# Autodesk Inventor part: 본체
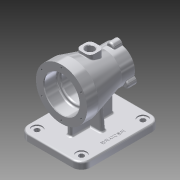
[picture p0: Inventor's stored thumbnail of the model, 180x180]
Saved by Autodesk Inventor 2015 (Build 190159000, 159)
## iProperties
Created: 2021-10
Part Number: 본체
Material: 알루미늄 6061
Document SubType Name: Modeling
Designer: 10259o
Density: 2.7 g/cm^3
Appearance: 알루미늄 - 평지
Mass: 1228.33 g
Surface Area: 906.538 cm^2
Volume: 454.938 cm^3
Author: 10259o
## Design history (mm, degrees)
sketch "스케치1"
  geometry: L1 (0, -100)-(0, 0); L2 (31, 0)-(31, -23); L3 (31, -23)-(25, -23); L4 (25, -23)-(25, -70); L5 (25, -70)-(19, -70); L6 (19, -70)-(19, -100); L7 (19, -100)-(29, -100); L8 (29, -100)-(29, -77); L9 (29, -77)-(45, -20); L10 (45, -20)-(45, 0); L11 (45, 0)-(31, 0); 2 further points
  constraints: 22 end point, 5 perpendicular, 2 horizontal alignment, 2 midpoint, 1 horizontal, 1 parallel, 1 vertical
  dimensions: "d0" = 100 distance between parallel lines of L7 L11; "d2" = 38 diameter of L6 L1; "d3" = 30 distance between parallel lines of L5 L7; "d4" = 47 distance between parallel lines of L3 L5; "d5" = 50 diameter of L4 L1; "d6" = 62 diameter of L2 L1; "d7" = 90 diameter of L10 L1; "d8" = 23 distance from line of L8.end L7; "d9" = 20 distance of L9.end L10.end; "d10" = 58 diameter of L8 L1
revolve "회전1" sketch "스케치1" stored, may be unused: angle "d11" = 90 deg
node "작업 평면1"
sketch "스케치2"
  geometry: L1 (55, -120)-(-55, -120); L2 (-55, -120)-(-55, 20); L3 (-55, 20)-(55, 20); L4 (55, 20)-(55, -120); L5 (55, -50)-(-55, -50); L6 (0, 0)-(0, -99.524); 1 further point
  constraints: 12 end point, 3 midpoint, 2 parallel, 1 horizontal, 1 perpendicular, 1 vertical, 1 vertical alignment
  dimensions: "d13" = 140 distance between parallel lines of L1 L3; "d14" = 110 distance of L2.end L3.end; "d15" = 50 distance from line of L5 L6.start
extrude "돌출1" join sketch "스케치2" distance "d16" = 12; taper "d17" = 0 deg
sketch "스케치3"
  geometry: L1 (-4, 13)-(4, 13); L2 (4, 13)-(4, 87); L3 (4, 87)-(-4, 87); L4 (-4, 87)-(-4, 13); L5 (-55, -20)-(-55, 120) reference; L6 (-55, 50)-(55, 50); L7 (55, 120)-(55, -20) reference; 2 further points
  constraints: 10 end point, 3 midpoint, 2 parallel, 1 horizontal, 1 perpendicular, 1 vertical alignment
  dimensions: "d18" = 8 distance of L2.end L3.end; "d19" = 74 distance between parallel lines of L1 L3; "d20" = 37 distance between parallel lines of L3 L6
extrude "돌출2" join sketch "스케치3" stored distance "d21" = 0; taper "d22" = 0 deg
node "작업 평면2"
sketch "스케치4"
  geometry: L1 (0, 12)-(110, 12) reference; L2 (79, 12)-(75.149, 56.019); L3 (75.149, 56.019)-(59, 56.019); L4 (59, 12)-(59, 53.277) reference; L5 (59, 56.019)-(59, 12); 1 further point
  constraints: 6 end point, 2 point on line, 1 collinear, 1 horizontal
  dimensions: "d24" = 95 deg angle of L1 L2; "d91" = 24 horizontal distance of point (55, 82) L2.start
extrude "돌출3" join sketch "스케치4" stored distance "d26" = 8; taper "d27" = 0 deg
node "작업 평면3"
sketch "스케치5"
  geometry: L1 (12.5, -62.5)-(-12.5, -62.5); L2 (-12.5, -62.5)-(-12.5, -37.5); L3 (-12.5, -37.5)-(12.5, -37.5); L4 (12.5, -37.5)-(12.5, -62.5); L5 (-55, -120)-(-55, 20) reference; L6 (-55, -50)-(55, -50); L7 (55, 20)-(55, -120) reference; L8 (55, -120)-(-55, -120) reference; L9 (0, -120)-(0, 20); L10 (-55, 20)-(55, 20) reference; C1 r 7.5 at (0, -50); 3 further points
  constraints: 12 end point, 7 midpoint, 2 parallel, 2 point on line, 1 centre point, 1 horizontal, 1 perpendicular
  dimensions: "d29" = 25 distance between parallel lines of L4 L2; "d30" = 25 distance of L1.end L2.end; "d31" = 15 diameter of C1
extrude "돌출4" join sketch "스케치5" stored distance "d32" = 8; taper "d33" = 0 deg
sketch "스케치6"
  geometry: C1 r 7.5 at (0, -50) reference; C2 r 8 at (0, -50); 1 further point
  constraints: 1 centre point, 1 coincident
extrude "돌출5" cut sketch "스케치6" distance "d34" = 31.5; taper "d35" = 0 deg
sketch "스케치7"
  geometry: A1 r 29 centre (0, 0) between (0, 29) and (-6.949, 28.155) reference; A2 r 7 centre (0, 29) between (6.949, 28.155) and (-6.949, 28.155)
  constraints: 5 point on circle, 1 centre point, 1 vertical alignment
  dimensions: "d36" = 14 diameter of A2
extrude "돌출6" join sketch "스케치7" distance "d37" = 15; taper "d38" = 0 deg
sketch "스케치8"
  geometry: A1 r 7 centre (0, 0) between (6.949, -0.845) and (-6.949, -0.845) reference; 1 further point
  constraints: 1 coincident
hole "구멍1" sketch "스케치8" at (0, 0) diameter "d39" = 3.242; stored, may be unused: countersink angle "d43" = 90 deg, drill point angle "d45" = 118 deg; dims "d40" = 9, "d41" = 4, "d42" = 2, "d44" = 11
sketch "스케치9" dims "d49" = 80
  geometry: C1 r 31 at (0, 0) reference; C2 r 45 at (0, 0) reference; 2 further points
  constraints: 2 vertical alignment, 1 coincident, 2 other
hole "구멍2" sketch "스케치9" at (0, 40) diameter "d50" = 3.242; stored, may be unused: countersink angle "d54" = 90 deg, drill point angle "d56" = 118 deg; dims "d51" = 9, "d52" = 4, "d53" = 2, "d55" = 11
sketch "스케치10"
  geometry: L1 (55, 120)-(-55, 120) reference; L2 (-55, 120)-(-55, -20) reference; L3 (-55, -20)-(55, -20) reference; C1 r 9 at (-39, 104); C2 r 9 at (-39, -4); 1 further point
  constraints: 2 centre point, 1 vertical alignment
  dimensions: "d60" = 16 distance from line of L2 C2.centre; "d61" = 16 distance from line of L3 C2.centre; "d62" = 16 distance from line of L1 C1.centre; "d63" = 18 diameter of C1; "d64" = 18 diameter of C2
extrude "돌출7" cut sketch "스케치10" distance "d65" = 2; taper "d66" = 0 deg
sketch "스케치11"
  geometry: C1 r 9 at (0, 0) reference; C2 r 4.5 at (0, 0); C3 r 9 at (0, -108) reference; C4 r 4.5 at (0, -108); 1 further point
  constraints: 2 centre point, 2 coincident
  dimensions: "d67" = 9 diameter of C4; "d68" = 9 diameter of C2
extrude "돌출8" cut sketch "스케치11" stored distance "d69" = 2; taper "d70" = 0 deg
fillet "모깎기1" dims "d71" = 16
fillet "모깎기2" dims "d72" = 3
fillet "모깎기3" dims "d73" = 3
fillet "모깎기4" dims "d74" = 3
fillet "모깎기5" dims "d75" = 3
fillet "모깎기6" dims "d76" = 8
fillet "모깎기7" dims "d77" = 1
chamfer "모따기1" distance "d78" = 1; stored, may be unused: second distance "d79" = 2, angle "d80" = 45 deg
chamfer "모따기2" distance "d81" = 1; stored, may be unused: second distance "d82" = 2, angle "d83" = 45 deg
fillet "모깎기8" dims "d84" = 3
fillet "모깎기9" dims "d85" = 1
fillet "모깎기10" dims "d86" = 3
fillet "모깎기11" dims "d87" = 3
sketch "스케치12"
  geometry: L1 (-52, -4)-(-52, 104) reference; L2 (55, -4)-(55, 104) reference; 3 further points
  constraints: 1 horizontal alignment, 1 midpoint, 1 other
  dimensions: "d88" = 15 distance from line of L2 point (40, 50)
feature "엠보싱1" sketch "스케치12" dims "d13" = 140, "d14" = 110, "d15" = 50, "d89" = 0.5, "d90" = 0
node "솔리드1"
mirror "대칭1"
pattern_circular "원형 패턴1" dims angle "d47" = 360 deg
pattern_circular "원형 패턴2" dims angle "d58" = 360 deg
mirror "대칭2"
other parameters: "d12" = -82, "d28" = 45
